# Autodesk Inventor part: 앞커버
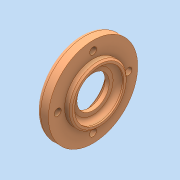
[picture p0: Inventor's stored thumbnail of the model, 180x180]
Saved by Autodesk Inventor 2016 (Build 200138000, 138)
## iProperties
Created: 2024-08
Part Number: 앞커버
Material: 일반
Document SubType Name: Modeling
Designer: pc-7
Density: 1 g/cm^3
Appearance: 기본값
Author: jhkim
Sending System: Autodesk Inventor 2025
Preprocessor: ST-DEVELOPER v20
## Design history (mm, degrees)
node "앞커버1"
node "솔리드2"
node "솔리드1"
